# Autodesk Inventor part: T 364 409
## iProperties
Company: Mayer & Müller AG Schaltgeräte
Created: 2006-03
Part Number: T 364 409
Material: 1.4301
Document SubType Name: Modeling
Designer: I.Baliuc
Description: Grundplatte
Density: 7.86 g/cm^3
HalbzeugNorm: DIN 174
Abmessung: Fl. 120 x 12
Author: T.Messerschmitt
Keywords: 380094
Revision Number: 364409
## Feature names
1. Extrusion2
2. Bohrung1 [Hole]
